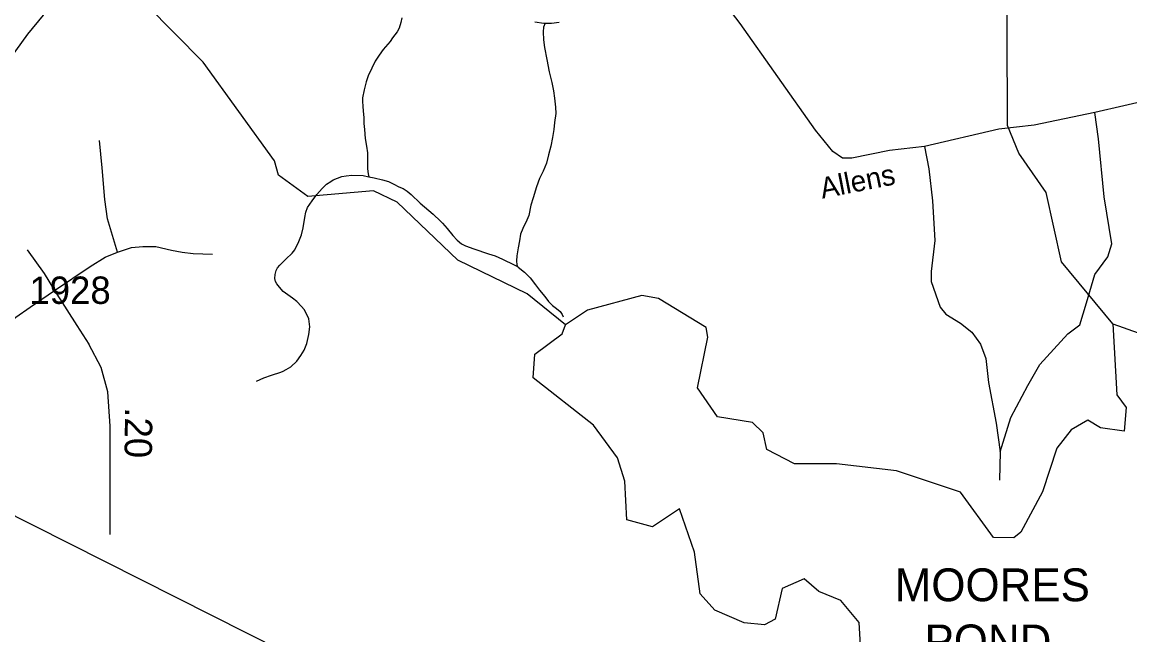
# Model space of a CAD drawing. Extents: x 2126262 to 2293712, y 749403 to 919119.
# Drawn here: x 2165466 to 2170526, y 811845 to 814643 of the extents above; entities that cross this region are included whole.
import ezdxf

# ---------------------------------------------------------------- set-up
doc = ezdxf.new("R2010")
doc.units = 0
for name, color, linetype in [('Exist Boundary Political CountyLine', 7, 'Continuous'), ('Exist Hydrographic Creek Single Shore', 7, 'Continuous'), ('Exist Hydrographic Lake Shore', 7, 'Continuous'), ('Exist Hydrographic Misc Water Feature', 7, 'Continuous'), ('Exist Hydrographic Pond Over 1500 Sq Ft Label', 7, 'Continuous'), ('Exist Road Non-System Type 51', 7, 'Continuous'), ('Exist Road Non-System Type 51 Label', 7, 'Continuous'), ('Exist Road Secondary Mileage Hundredths English Label', 7, 'Continuous'), ('Exist Road Secondary Type 51 Attributed', 7, 'Continuous'), ('Exist Road Secondary Type 51 Number Label', 7, 'Continuous')]:
    doc.layers.add(name, color=color, linetype=linetype)

msp = doc.modelspace()

# ---------------------------------------------------------------- linework, layer by layer
at = {"layer": 'Exist Boundary Political CountyLine'}
msp.add_lwpolyline([(2192122.8, 787074.7), (2191946.5, 788439.9), (2191462.4, 794425.4), (2179295.7, 796467.1), (2169584.9, 810291.7), (2151370.7, 819485.6), (2149836.3, 820237.8), (2146070.6, 821922.1), (2135812.5, 826366.6), (2134133.6, 827149.9), (2133839.4, 827270.1)], dxfattribs=at)
at = {"layer": 'Exist Hydrographic Creek Single Shore'}
msp.add_lwpolyline([(2167948.7, 813261.2), (2167773.6, 813402.6), (2167455.8, 813556.8), (2167179.8, 813821.6), (2167070.7, 813873.1), (2166770.7, 813846.4), (2166636.6, 813944.4), (2166619.8, 814010.3), (2166292.7, 814460), (2166032.7, 814724.5), (2165923.6, 814966.3), (2165905.6, 815065)], dxfattribs=at)
at = {"layer": 'Exist Hydrographic Lake Shore'}
for points in [[(2170447.7, 813265.5), (2170564.8, 813223.7), (2170615.6, 813058.6), (2170682.7, 812991.6), (2170740.7, 813000.3), (2170790.7, 813094.4), (2170780.7, 813327.5), (2170963.6, 813517.3), (2171146.7, 813487.3)], [(2170447.7, 813265.5), (2170466.7, 812940.3), (2170508.6, 812883.7), (2170500.6, 812775.5), (2170392.7, 812790.9), (2170333.7, 812824.9), (2170258.6, 812780.5), (2170192.6, 812696.6), (2170127.6, 812497.8), (2170028.7, 812312.9), (2169995.7, 812287.3), (2169903.7, 812289.2), (2169752.7, 812495.7), (2169460.8, 812593.6), (2169185.6, 812625.5), (2168993.6, 812626.2), (2168868.6, 812691.1), (2168851.8, 812766.9), (2168801.7, 812813.9), (2168642.6, 812840.1), (2168550.7, 812973.2), (2168598.7, 813205.1), (2168590.7, 813248), (2168372.7, 813380.4), (2168297.7, 813395.1), (2168048.6, 813328), (2167948.7, 813261.2)], [(2169298.6, 811744), (2169289.7, 811901.6), (2169205.7, 812001.8), (2169105.6, 812043.3), (2169038.8, 812100.4), (2168938.7, 812056.5), (2168905.7, 811916.1), (2168856.7, 811890.8), (2168764.6, 811899.3), (2168630.7, 811957.8), (2168563.7, 812031.4), (2168537.6, 812222.2), (2168469.7, 812420.5), (2168345.7, 812337.8), (2168228.6, 812369.7), (2168219.6, 812547), (2168185.7, 812652.7), (2168076.7, 812802.6), (2167800.7, 813018.2), (2167807.6, 813126.4), (2167932.7, 813218.9), (2167948.7, 813261.2)]]:
    msp.add_lwpolyline(points, dxfattribs=at)
at = {"layer": 'Exist Hydrographic Misc Water Feature'}
for points in [[(2170447.7, 813265.5), (2170213.7, 813549.1), (2170144.6, 813865.5), (2170018.7, 814045.3), (2169967.6, 814171), (2169963.8, 815053.5), (2169928.7, 815264.3), (2169793.8, 815552.4), (2169792.7, 815746), (2169883.6, 815895), (2169882.8, 816105.1), (2169939.8, 816287.6), (2169880.7, 816479), (2169879.7, 816662.8), (2169786.6, 816796), (2169277.7, 816973.8), (2169060.7, 817083.2), (2168992.6, 817215.9)], [(2167200.4, 814663), (2167196.5, 814641.3), (2167188.3, 814615.3), (2167178.9, 814598.9), (2167158.8, 814571.1), (2167146.9, 814555.1), (2167115.3, 814518.9), (2167097.5, 814492.8), (2167079, 814464.7), (2167063.6, 814432.6), (2167047.6, 814398.5), (2167037.8, 814370.3), (2167028.1, 814334.5), (2167020.4, 814298.3), (2167020.4, 814280.5), (2167022.6, 814260.3), (2167024.5, 814236.4), (2167026.7, 814208.5), (2167027.1, 814180.5), (2167030.8, 814152.3), (2167033.3, 814112.6), (2167039.4, 814076.4), (2167043.9, 814046.5), (2167043.5, 814016.5), (2167044.1, 813994.5), (2167044.3, 813972.6), (2167046.2, 813950.4), (2167050.3, 813936.4)], [(2167855.9, 814638.9), (2167848.4, 814621), (2167846.3, 814599), (2167848.4, 814563), (2167852.7, 814527.1), (2167863.3, 814473.1), (2167873.6, 814417.2), (2167885.9, 814367), (2167893.7, 814329.3), (2167897.8, 814295.5), (2167902.3, 814255.5), (2167904.5, 814225.5), (2167898.6, 814185.4), (2167894.9, 814153.1), (2167889, 814117.1), (2167881.6, 814077.2), (2167871.3, 814037), (2167862.1, 813999), (2167845.9, 813962.9), (2167829.9, 813928.8), (2167816.4, 813890.7), (2167800.4, 813840.8), (2167790.5, 813807), (2167781.3, 813760.9), (2167771, 813738.5), (2167753.8, 813700.6), (2167743.4, 813674.6), (2167738, 813644.5), (2167732.3, 813612.5), (2167726.3, 813576.5), (2167724.5, 813552.4), (2167726.6, 813534.3), (2167728.6, 813526.7)], [(2167808.2, 814644.6), (2167850, 814639), (2167855.9, 814638.9)], [(2167855.9, 814638.9), (2167884, 814639.2), (2167920.1, 814643.4)], [(2166536.9, 813003.8), (2166569.6, 813018.3), (2166605.7, 813030.3), (2166647.6, 813044.7), (2166659.3, 813048.6), (2166673, 813056.7), (2166693.3, 813068.6), (2166721, 813094.8), (2166739, 813120.9), (2166754.8, 813145.3), (2166766.7, 813175.1), (2166776.5, 813217.1), (2166780.2, 813251.4), (2166775.9, 813287.4), (2166765.9, 813311.2), (2166754, 813331.2), (2166741.9, 813344.9), (2166721.6, 813367), (2166701.5, 813383), (2166659.1, 813412.5), (2166641.2, 813432.3), (2166629.3, 813448.3), (2166623, 813458.2), (2166621.1, 813472.3), (2166622.8, 813490.3), (2166626.7, 813508.3), (2166632.8, 813520.4), (2166643.1, 813532.6), (2166670.5, 813560.5), (2166700.5, 813588.8), (2166712.6, 813602.8), (2166729.8, 813640.8), (2166741.7, 813671.1), (2166750.1, 813703.1), (2166757.5, 813751), (2166761.6, 813774.8), (2166769.6, 813797.1), (2166791.1, 813827.1), (2166812.8, 813855.5), (2166837, 813883.5), (2166856.5, 813903.6), (2166876.8, 813915.5)], [(2166876.8, 813915.5), (2166886.7, 813923.8), (2166926.2, 813937.7), (2166946.1, 813942), (2166972.4, 813944.1), (2167024.5, 813942.3), (2167050.3, 813936.4)], [(2167050.3, 813936.4), (2167074.3, 813932.8), (2167112.2, 813923), (2167140.1, 813915.1), (2167164.5, 813903.3), (2167186.9, 813891.4), (2167206.7, 813883.5), (2167224.6, 813871.5), (2167242.8, 813855.7), (2167285.1, 813816.1), (2167343.1, 813766.3), (2167377.3, 813734.4), (2167387.2, 813724.7), (2167407.5, 813700.6), (2167433.5, 813668.7), (2167453.8, 813647), (2167473.5, 813631), (2167492, 813621.3), (2167530.1, 813607.4), (2167596.1, 813585.7), (2167626.3, 813575.8), (2167660.3, 813560.1), (2167714.3, 813534.6), (2167728.6, 813526.7)], [(2167728.6, 813526.7), (2167732.5, 813524.5), (2167760.4, 813500.8), (2167786.6, 813474.9), (2167810.6, 813442.8), (2167829.3, 813419), (2167853.3, 813389.4), (2167871.3, 813367.6), (2167889.6, 813349.4), (2167907.6, 813335.7), (2167923.6, 813321.6), (2167933.7, 813307.8), (2167937.3, 813297.9)]]:
    msp.add_lwpolyline(points, dxfattribs=at)
at = {"layer": 'Exist Road Non-System Type 51'}
msp.add_line((2169933, 812680.2), (2169930.2, 812551.7), dxfattribs=at)
for points in [[(2169587.6, 814076), (2169428.6, 814056.5), (2169256.9, 814021.6), (2169213.7, 814021.6), (2169169, 814052.3), (2169089.5, 814150), (2168745.6, 814636.7), (2168578.8, 814858.1)], [(2165645.4, 814741.9), (2165561.9, 814676), (2165490.5, 814588), (2165389.4, 814447.3), (2165253.1, 814277.9), (2165114.6, 814084.4), (2165034.7, 813962.7), (2164886.5, 813760.5), (2164656.4, 813447.2), (2164476.7, 813205.9)], [(2172293, 813979.3), (2172133.4, 813989.6), (2172018.9, 814007.7), (2171789.2, 814167.8), (2171715.3, 814208.3), (2171644.1, 814219.5), (2171444.6, 814206.9), (2171391.6, 814218.1), (2171297.6, 814251.3), (2171209.7, 814311.3), (2171112, 814354.6), (2171040.8, 814364.4), (2170905.5, 814354.6), (2170630.6, 814291.8), (2170366.2, 814231)], [(2170366.2, 814231), (2170089.2, 814173.1), (2169927.4, 814154.9), (2169587.6, 814076)], [(2169933, 812680.2), (2169983.2, 812838), (2170059.9, 812983.3), (2170115.1, 813078.9), (2170243.4, 813220), (2170297.1, 813261.2), (2170327.8, 813361.7), (2170365.5, 813490.2), (2170426.2, 813571.9), (2170444.3, 813630.5), (2170409.5, 813845.6), (2170382.3, 814110.2), (2170366.2, 814231)], [(2165901.8, 813592.2), (2165855.5, 813744.8), (2165843.4, 813834), (2165831.4, 813978.1), (2165820.3, 814103.3)], [(2169587.6, 814076), (2169608.6, 813974.1), (2169625.3, 813827.4), (2169635.8, 813646.6), (2169619, 813504.2), (2169619, 813458.1), (2169659.5, 813340.8), (2169685.3, 813309.3), (2169752.3, 813268.8), (2169803.9, 813227), (2169844.4, 813172.5), (2169868.1, 813106.9), (2169880.6, 812997.9), (2169914.8, 812811.5), (2169933, 812680.2)], [(2165489, 813603), (2165567.4, 813494.5), (2165614.1, 813417.7)], [(2165901.8, 813592.2), (2165966.1, 813614.5), (2166017.6, 813617.9), (2166077.6, 813617.9), (2166147.9, 813602.4), (2166197.7, 813592.2), (2166247.4, 813587), (2166336.6, 813583.6)], [(2165614.1, 813417.7), (2165776.5, 813527), (2165845.2, 813569.9), (2165901.8, 813592.2)], [(2164957.4, 812767.7), (2165159, 813023.1), (2165230.2, 813112.1), (2165313.2, 813192.2), (2165437.7, 813295.9), (2165503.7, 813341.9), (2165614.1, 813417.7)], [(2165614.1, 813417.7), (2165715.9, 813257.5), (2165770.9, 813172.4)]]:
    msp.add_lwpolyline(points, dxfattribs=at)
at = {"layer": 'Exist Road Secondary Type 51 Attributed'}
msp.add_lwpolyline([(2165868.7, 812302.8), (2165867.7, 812798.5), (2165857.7, 812955.4), (2165826.8, 813065.6), (2165770.9, 813172.4)], dxfattribs=at)

# ---------------------------------------------------------------- texts
at = {"layer": 'Exist Hydrographic Pond Over 1500 Sq Ft Label'}
for s, p in [('MOORES', (2169452.1, 811998.1)), ('POND', (2169588, 811741.7))]:
    msp.add_text(s, height=150, dxfattribs=at).set_placement(p)
at = {"layer": 'Exist Road Non-System Type 51 Label'}
msp.add_text('Allens', height=95, rotation=11.1449, dxfattribs=at).set_placement((2169121.1, 813836.8))
at = {"layer": 'Exist Road Secondary Mileage Hundredths English Label'}
msp.add_text('.20', height=125, rotation=269.4026, dxfattribs=at).set_placement((2165936.4, 812884.7))
at = {"layer": 'Exist Road Secondary Type 51 Number Label'}
msp.add_text('1928', height=125, dxfattribs=at).set_placement((2165499.2, 813356.4))

doc.saveas('drawing.dxf')
